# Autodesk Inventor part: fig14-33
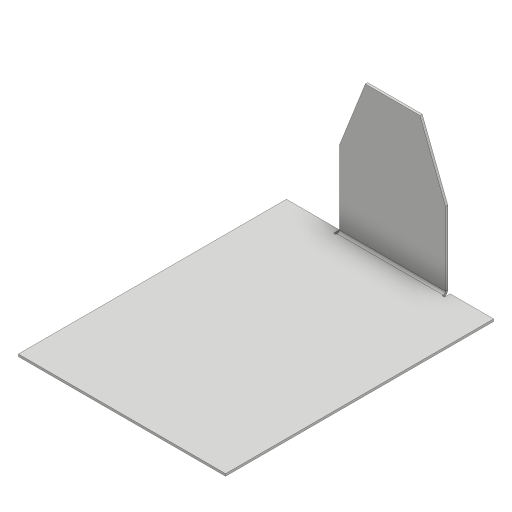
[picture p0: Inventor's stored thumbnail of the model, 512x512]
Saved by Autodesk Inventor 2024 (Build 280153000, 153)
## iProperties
Created: 2017-05
Part Number: fig14-33
Material: Generic
Document SubType Name: Sheet Metal
Designer: CADCIM 00
Density: 1 g/cm^3
Sheet Metal Rule: Default_mm
Appearance: Default
Author: CADCIM 00
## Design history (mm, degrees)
node "Face1"
  sketch "Sketch1"
    geometry: L1 (0, 0)-(45.649, 0); L2 (45.649, 0)-(45.649, 59.054); L3 (45.649, 59.054)-(0, 59.054); L4 (0, 59.054)-(0, 0)
    constraints: 8 end point, 2 parallel, 1 horizontal, 1 perpendicular
node "Face2"
  sketch "Sketch2"
    geometry: L1 (12.162, -17.144)-(17.899, -31.705); L2 (17.899, -31.705)-(29.912, -31.705); L3 (29.912, -31.705)-(35.56, -17.144); L4 (35.56, -17.144)-(12.162, -17.144); 1 further point
    constraints: 8 end point, 1 horizontal, 1 parallel
body "Solid1"
face "Plate1" dims "d0" = 0.5 (= Thickness)
face "Plate2" dims "d0" = 0.5 (= Thickness), "d1" = 0.5 (= BendRadius), "d2" = 0.5 (= BendReliefWidth), "d4" = 1 (= MinimumRemnant)
bend "Bend1" dims "d0" = 0.5 (= Thickness), "d1" = 0.5 (= BendRadius), "d2" = 0.5 (= BendReliefWidth), "d3" = 0.25 (= BendReliefDepth), "d4" = 1 (= MinimumRemnant), "d5" = 0.5 (= TransitionRadius), "SeamGap" = 0.01
other parameters: "Thickness" = 0.5, "BendRadius" = 0.5 (= Thickness), "BendReliefWidth" = 0.5 (= Thickness), "BendReliefDepth" = 0.25 (= 0.5 x Thickness), "CornerReliefSize" = 2 (= 4 x Thickness), "MinimumRemnant" = 1 (= 2 x Thickness), "TransitionRadius" = 0.5 (= BendRadius), "JacobiRadiusSize" = 0.5 (= BendRadius), "GapSize" = 0.5 (= Thickness)
